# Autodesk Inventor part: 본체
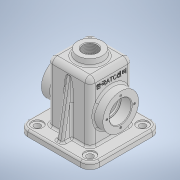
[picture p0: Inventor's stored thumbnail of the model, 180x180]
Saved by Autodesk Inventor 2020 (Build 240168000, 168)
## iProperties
Created: 2021-07
Part Number: 본체
Material: 일반
Document SubType Name: Modeling
Designer: Owner
Density: 1 g/cm^3
Appearance: 기본값
Mass: 278.272 g
Surface Area: 858.464 cm^2
Volume: 278.272 cm^3
Author: Owner
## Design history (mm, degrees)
sketch "스케치4"
  geometry: L1 (34, -34)-(-34, -34); L2 (-34, -34)-(-34, 34); L3 (-34, 34)-(34, 34); L4 (34, 34)-(34, -34); L5 (34, -34)-(-34, 34); L6 (-34, -34)-(34, 34); 1 further point
  constraints: 12 end point, 2 midpoint, 2 parallel, 1 horizontal, 1 perpendicular
  dimensions: "d11" = 68 distance of L2.end L3.end; "d12" = 68 distance of L1.end L2.end
extrude "돌출4" new body sketch "스케치4" distance "d13" = 105; taper "d14" = 0 deg
fillet "모깎기1" dims "d15" = 8
feature "쉘1" dims "d16" = 5
sketch "스케치6"
  geometry: L1 (-29, -26)-(-29, 26) reference; L2 (-26, 29)-(26, 29) reference; L3 (29, 26)-(29, -26) reference; L4 (26, -29)-(-26, -29) reference; L5 (-34, -26)-(-34, 26) reference; L6 (26, -34)-(-26, -34) reference; L7 (34, 26)-(34, -26) reference; L8 (-26, 34)-(26, 34) reference; L9 (-57, 57)-(57, 57); L10 (57, 57)-(57, -57); L11 (57, -57)-(-57, -57); L12 (-57, -57)-(-57, 57); L13 (-57, 57)-(57, -57); L14 (57, 57)-(-57, -57); A1 r 3 centre (-26, -26) between (-29, -26) and (-26, -29) reference; A2 r 3 centre (-26, 26) between (-26, 29) and (-29, 26) reference; A3 r 3 centre (26, 26) between (29, 26) and (26, 29) reference; A4 r 3 centre (26, -26) between (26, -29) and (29, -26) reference; A5 r 8 centre (-26, 26) between (-26, 34) and (-34, 26) reference; A6 r 8 centre (-26, -26) between (-34, -26) and (-26, -34) reference; A7 r 8 centre (26, -26) between (26, -34) and (34, -26) reference; A8 r 8 centre (26, 26) between (34, 26) and (26, 34) reference; 1 further point
  constraints: 12 end point, 2 midpoint, 2 parallel, 1 horizontal, 1 perpendicular
  dimensions: "d17" = 114 distance of L10.end L11.end; "d18" = 114 distance of L9.end L10.end
extrude "돌출5" join sketch "스케치6" distance "d19" = 10; taper "d20" = 0 deg
fillet "모깎기2" dims "d21" = 15
sketch "스케치7"
  geometry: A1 r 15 centre (42, -42) between (42, -57) and (57, -42) reference; 2 further points
  constraints: 1 coincident
hole "구멍1" sketch "스케치7" at (42, -42) diameter "d22" = 10; stored, may be unused: countersink angle "d26" = 90 deg, drill point angle "d28" = 0 deg; dims "d23" = 20, "d24" = 18, "d25" = 2, "d27" = 10
node "작업 평면1"
sketch "스케치8"
  geometry: C1 r 20 at (0, 0); 1 further point
  constraints: 1 centre point, 1 coincident
  dimensions: "d30" = 40 diameter of C1
extrude "돌출6" join sketch "스케치8" stored distance "d31" = 10; taper "d32" = 8 deg
sketch "스케치9"
  geometry: C1 r 20 at (0, 0) reference; 2 further points
  constraints: 1 coincident
hole "구멍2" sketch "스케치9" at (0, 0) diameter "d33" = 22.83494; stored, may be unused: countersink angle "d37" = 90 deg, drill point angle "d39" = 0 deg; dims "d34" = 50, "d35" = 18, "d36" = 2, "d38" = 59.3
chamfer "모따기1" distance "d40" = 1; stored, may be unused: second distance "d41" = 2, angle "d42" = 45 deg
node "작업 평면2"
sketch "스케치10"
  geometry: L1 (0, -42)-(0, 42) reference; C1 r 28.5 at (52, 0); 2 further points
  constraints: 1 centre point, 1 horizontal alignment, 1 midpoint
  dimensions: "d44" = 57 diameter of C1; "d45" = 52 distance from line of L1 C1.centre
extrude "돌출7" join sketch "스케치10" stored distance "d46" = 10; taper "d47" = 0 deg
sketch "스케치11"
  geometry: C1 r 28.5 at (0, 0) reference; 2 further points
  constraints: 1 coincident
hole "구멍3" sketch "스케치11" at (0, 0) diameter "d48" = 30; stored, may be unused: countersink angle "d52" = 90 deg, drill point angle "d54" = 0 deg; dims "d49" = 70, "d50" = 35, "d51" = 17, "d53" = 50
fillet "모깎기3" dims "d55" = 3
sketch "스케치12" dims "d56" = 44
  geometry: C1 r 28.5 at (0, 0) reference; 3 further points
  constraints: 2 vertical alignment, 1 coincident, 2 other
hole "구멍4" sketch "스케치12" at (0, 22) diameter "d57" = 3.242; stored, may be unused: countersink angle "d61" = 90 deg, drill point angle "d63" = 118 deg; dims "d58" = 8, "d59" = 18, "d60" = 2, "d62" = 10
fillet "모깎기4" dims "d70" = 3
sketch "스케치13"
  geometry: L1 (46.58, -42.55)-(10, -49); L2 (10, -42)-(10, -57) reference; L3 (10, -57)-(0, -57) reference; 1 further point
  constraints: 2 end point, 1 point on line
  dimensions: "d71" = 8 distance from line of L1.end L3; "d72" = 10 deg angle of L1 L3
feature "리브1" sketch "스케치13" dims "d73" = 1, "d74" = 10, "d75" = 0, "d76" = 0, "d77" = 1, "d78" = 1
fillet "모깎기5" dims "d79" = 3
fillet "모깎기6" dims "d80" = 3
chamfer "모따기2" distance "d81" = 1; stored, may be unused: second distance "d82" = 2, angle "d83" = 45 deg
fillet "모깎기7" dims "d84" = 0.3
sketch "스케치14"
  geometry: L1 (6, 18)-(46, 18) reference; C1 r 28.5 at (26, -45) reference; 2 further points
  constraints: 1 vertical alignment, 1 other
  dimensions: "d85" = 25 distance from line of point (26, -7) L1
feature "엠보싱1" sketch "스케치14" dims "d86" = 0.5, "d87" = 0
node "솔리드2"
mirror "미러1"
mirror "미러2"
pattern_circular "원형 패턴1" dims angle "d65" = 360 deg
mirror "미러3"
mirror "미러4"
mirror "미러5"
mirror "미러6"
pattern_circular "원형 패턴2" dims angle "d68" = 360 deg
mirror "미러7"
node "투영된 루프2"
feature "A9D066F2-1C7D-4E18-AEED-F7BC21143FA4" dims "d22" = 10, "d23" = 20, "d24" = 18, "d25" = 2, "d26" = 90 deg, "d27" = 10, "d28" = 0
other parameters: "d29" = -115, "d43" = 49
